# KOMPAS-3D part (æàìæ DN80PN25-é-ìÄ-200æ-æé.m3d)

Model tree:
1. Объединить компоненты:1  (labels: СЕНС DN80PN25-В-НО-200С)
2. Эскиз:1
3. Операция выдавливания:1
     Расстояние 1 = 14
4. Фаска:1
     Угол = 45; Длина 1 = 2; Длина 2 = 2

Referenced files in D:\Савин\!СЕНСОР\3D для заказчика\!Новый перечень\СЕНС\7. СЕНС-В-НО-200С\DN80\: СЕНС DN80PN25-В-НО-200С.a3d
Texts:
  СЕНС DN80PN25-В-НО-200С-СВ
  ООО НПП Сенсор
  СЕНС DN80PN25-В-НО-200С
